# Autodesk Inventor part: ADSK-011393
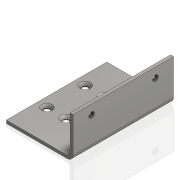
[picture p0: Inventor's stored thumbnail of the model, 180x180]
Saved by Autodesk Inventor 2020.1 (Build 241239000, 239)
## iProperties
Created: 2000-01
Part Number: ADSK-011393
Material: 1.0312 DC05
Description: FSHTPH,SC,CP,01,026,016,040,090,LUG,TRANSFER
Document SubType Name: Tôlerie
Designer: sspink
Density: 1 g/cm^3
Sheet Metal Rule: Stahlblech 1.0312 - DC05 -   3.0 mm
Appearance: Stahl
Mass: 30.0739 g
Surface Area: 216.871 cm^2
Volume: 30.0739 cm^3
Flat Pattern Width: 10.2286 cm
Flat Pattern Length: 10 cm
Flat Pattern Area: 102.286 cm^2
Sheet Metal Width: 102,286 mm
Sheet Metal Length: 100,000 mm
Sheet Metal Area: 10228,584 mm^2
Control State: 0
Checked Out: False
Master: False
Shininess: 60.0
Length Units: 11269
Angle Units: 11279
Time Units: 11290
Mass Units: 11283
Length Display Precision: 3
Angle Display Precision: 2
Compacted: True
Cutlength: 4.00 x 4.03 (17 SI)
Material Desc: SHEET,CRS,11 GA
Material_number: A084603
G_L: 100x102,3 mm
Thickness: 3,000 mm
Dimensions: 66,5x41x100 mm
Mass: 0,03 kg
Semi finished: Stahlblech 1.0312 - DC05 -   3.0 mm
DocNumber: ADSK-011393.ipt
Folder: 01 - Themengebiete\Simplification\01 - Packaging machine\
VDS_Category: 3D Komponenten
Density: 0.0
Volumn: 0.0
Area: 0.0
PropertySet Name: Model Information
Author: sspink
Revision Number: -
Title: angle
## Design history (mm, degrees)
node "Solide1"
  node "Extrusion1" dims "d7" = 100, "d8" = 0
  node "Hole1" dims "d15" = 5.5, "d16" = 10.4, "d17" = 6.35, "d18" = 90 deg, "d19" = 19.05, "d20" = 118 deg, "d44" = 6
  node "Hole2" dims "d26" = 5.5, "d27" = 9.525, "d28" = 6.35, "d29" = 60 deg, "d30" = 19.05, "d31" = 118 deg, "d46" = 6
  node "Bend1" dims "d39" = 3 (= BendRadius), "d40" = 3 (= BendReliefWidth), "d41" = 1.5 (= BendReliefDepth), "d42" = 6 (= MinimumRemnant), "d43" = 3 (= Thickness), "SeamGap" = 0.00508, "MinimumRemnant" = 6 (= 2 x Thickness), "BendReliefWidth" = 3 (= Thickness)
sketch "Sketch1"
  geometry: L1 (0, 0)-(-66.5, 0); L2 (-66.5, 0)-(-66.5, 3); L3 (-66.5, 3)-(0, 3); L4 (0, 3)-(0, 0); L5 (0, 3)-(-3, 3); L6 (-3, 3)-(-3, 41); L7 (-3, 41)-(0, 41); L8 (0, 41)-(0, 3)
  constraints: 16 end point, 4 parallel, 2 horizontal, 2 perpendicular
  dimensions: "d1" = 66.5 distance of L2.end L3.end; "d2" = 3 distance of L6.end L7.end (= Thickness); "d3" = 38 distance of L7.end L3.end; "d32" = 3 distance between parallel lines of L1 L3 (= Thickness)
sketch "Sketch2"
  geometry: L1 (50, 0)-(-50, 0) reference; L2 (50, 3)-(50, 66.5) reference; L3 (19, 57.1)-(-19, 57.1); L4 (-19, 57.1)-(-19, 38.1); L5 (-19, 38.1)-(19, 38.1); L6 (19, 38.1)-(19, 57.1); L7 (50, 66.5)-(-50, 66.5) reference; 4 further points
  constraints: 8 end point, 3 vertical alignment, 2 horizontal alignment, 2 midpoint, 2 parallel, 1 horizontal, 1 perpendicular
  dimensions: "d33" = 19 distance of point (19, 38.1) L3.start; "d34" = 38 distance of L3.start point (-19, 57.1); "d35" = 38.1 distance from line of L4.end L1
sketch "Sketch3"
  geometry: L1 (0, 0)-(100, 0) reference; L2 (18.25, -9.5)-(81.75, -9.5); 2 further points
  constraints: 2 end point, 2 midpoint, 1 horizontal, 1 vertical alignment
  dimensions: "d22" = 9.5 distance from line of L1 L2.start; "d45" = 63.5 distance of L2.start L2.end
node "FlatPattern"
node "Corps solides"
node "Corps surfaciques"
feature "Extrusion_mise_à_plat2" dims "d0" = 3 (derived)
other parameters: "d0" = 3.175, "Thickness" = 3 (derived), "BendRadius" = 3 (= Thickness), "BendReliefDepth" = 1.5 (= 0.5 x Thickness), "CornerReliefSize" = 12 (= 4 x Thickness), "TransitionRadius" = 3 (= BendRadius), "TailleRayonJacobi" = 3 (= BendRadius), "TailleJeu" = 3 (= Thickness)
